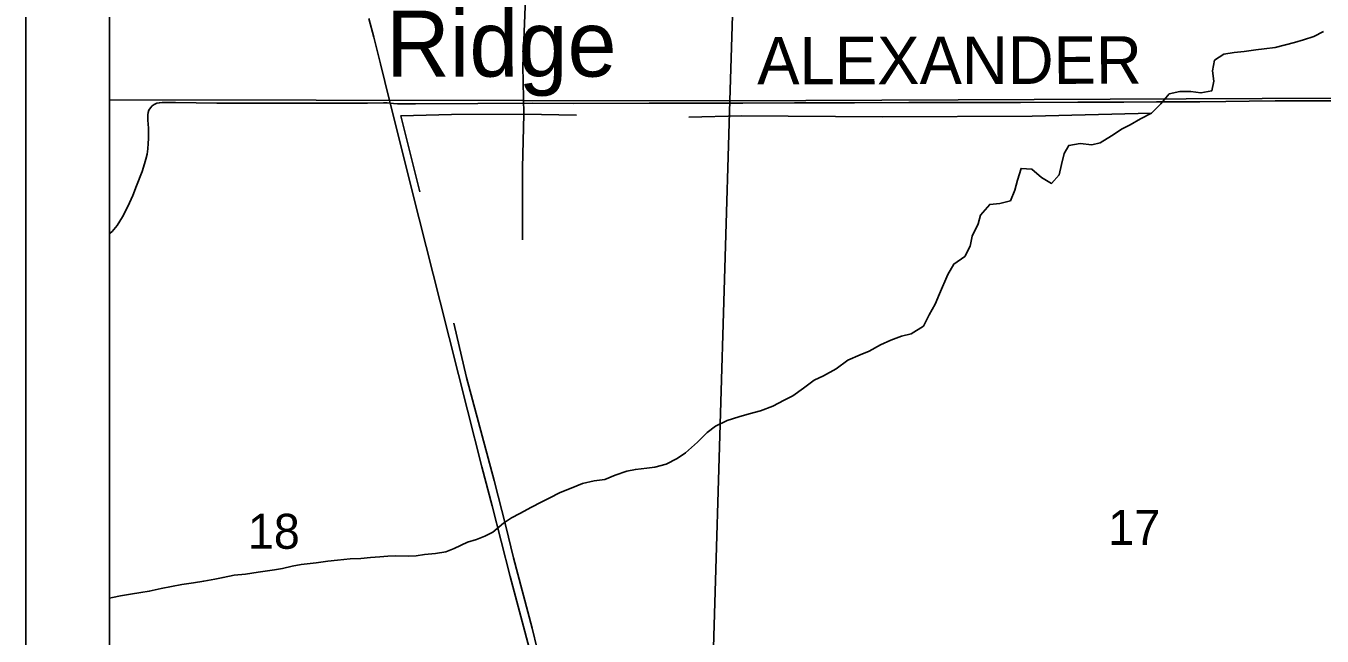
# Model space of a CAD drawing. Extents: x -8.3 to 42.1, y 0 to 22.
# Drawn here: x 2 to 3.551, y 15.682 to 16.412 of the extents above; entities that cross this region are included whole.
import ezdxf

# ---------------------------------------------------------------- set-up
doc = ezdxf.new("R2010")
doc.units = 0
for name, color, linetype in [('Default', 7, 'Continuous'), ('GM_X_Minor_River', 7, 'Continuous'), ('GM_X_Section', 7, 'Continuous'), ('GM_X_Section_Text', 7, 'Continuous'), ('GM_X_State_Route', 7, 'Continuous'), ('GM_X_Township_Road', 7, 'Continuous'), ('GM_X_Township_Road_Text', 7, 'Continuous'), ('GM_X_Unincorporated_Text', 7, 'Continuous'), ('SH_Cut_Line', 7, 'Continuous'), ('SH_Data', 7, 'Continuous')]:
    doc.layers.add(name, color=color, linetype=linetype)

msp = doc.modelspace()

# ---------------------------------------------------------------- linework, layer by layer
at = {"layer": 'Default'}
for points in [[(2.1, 17.3208), (2.1, 16.3231), (2.8424, 16.322), (2.8735, 17.321)], [(2.1, 16.3231), (2.1, 15.3156), (2.8124, 15.3208), (2.8424, 16.322)]]:
    msp.add_lwpolyline(points, close=True, dxfattribs=at)
at = {"layer": 'GM_X_Minor_River'}
for points in [[(2.5965, 16.562), (2.595, 16.4953), (2.5974, 16.4348), (2.5947, 16.3634), (2.5957, 16.306), (2.5942, 16.2418), (2.5941, 16.1558)], [(3.5528, 16.4047), (3.5413, 16.3989), (3.529, 16.395), (3.518, 16.3915), (3.4949, 16.3859)], [(3.4949, 16.3859), (3.4816, 16.384), (3.4717, 16.3828), (3.458, 16.3809), (3.4458, 16.3797), (3.4336, 16.3778), (3.4224, 16.3705), (3.4201, 16.358), (3.4217, 16.3454), (3.419, 16.3337), (3.4061, 16.3314), (3.394, 16.3329), (3.3807, 16.3329), (3.3681, 16.3302), (3.3582, 16.3183), (3.3469, 16.3072), (3.3338, 16.3004), (3.3215, 16.2931), (3.3118, 16.2885), (3.2991, 16.2801), (3.2856, 16.2717), (3.2756, 16.2694), (3.2616, 16.2709), (3.2479, 16.2686), (3.2423, 16.2589), (3.2393, 16.2457), (3.2366, 16.2332), (3.2272, 16.2232), (3.2153, 16.23), (3.2038, 16.2402), (3.1909, 16.241), (3.1867, 16.227), (3.1833, 16.215), (3.1781, 16.2022), (3.1654, 16.1991), (3.1533, 16.198), (3.1423, 16.185), (3.1393, 16.1748), (3.1324, 16.1602), (3.1298, 16.1481), (3.1234, 16.1357), (3.1102, 16.1266), (3.103, 16.1142), (3.0933, 16.0909), (3.088, 16.0786), (3.0808, 16.0658), (3.074, 16.0523), (3.0593, 16.0433), (3.0478, 16.0405), (3.0348, 16.0356), (3.0225, 16.0302), (3.009, 16.0226), (2.9982, 16.018), (2.9836, 16.0116), (2.9696, 16.0013), (2.9546, 15.993), (2.9431, 15.9877), (2.9306, 15.9781), (2.9178, 15.969), (2.9075, 15.964), (2.8936, 15.9568), (2.879, 15.9511), (2.8656, 15.9473), (2.853, 15.9439), (2.8392, 15.9393), (2.825, 15.9329), (2.8152, 15.9252), (2.8035, 15.9137), (2.7891, 15.9008), (2.7794, 15.8939), (2.766, 15.8874), (2.7526, 15.8836), (2.743, 15.8824), (2.7293, 15.8809), (2.719, 15.8789), (2.7052, 15.8739), (2.6929, 15.869), (2.68, 15.8674), (2.6662, 15.864), (2.6524, 15.8584), (2.6394, 15.8534), (2.6263, 15.8466), (2.6166, 15.8419), (2.6051, 15.8358), (2.5912, 15.8282), (2.5812, 15.8231), (2.5715, 15.8166), (2.5587, 15.8059), (2.549, 15.8012), (2.5391, 15.7973), (2.5283, 15.7938), (2.5126, 15.7863), (2.5026, 15.7824), (2.49, 15.7805), (2.477, 15.779), (2.4668, 15.7777), (2.4573, 15.7773), (2.4428, 15.7777), (2.433, 15.7772), (2.4235, 15.7763), (2.4124, 15.7755)], [(2.4712, 16.213), (2.4487, 16.3041), (2.5091, 16.3054), (2.5957, 16.306), (2.659, 16.3049)], [(3.3469, 16.3072), (3.2041, 16.3037), (3.0249, 16.3028), (2.856, 16.3038), (2.7933, 16.3022)], [(2.5119, 16.0559), (2.5271, 15.9908), (2.5604, 15.8678), (2.5744, 15.8131), (2.5836, 15.7752), (2.6059, 15.6909), (2.6239, 15.617)], [(2.4124, 15.7755), (2.4006, 15.7743), (2.3881, 15.7739), (2.3729, 15.7725), (2.3614, 15.7713), (2.3473, 15.7694), (2.3294, 15.7672), (2.3187, 15.7653), (2.3069, 15.7626), (2.2974, 15.7609), (2.2779, 15.7581), (2.2627, 15.7558), (2.249, 15.7543), (2.236, 15.7517), (2.2261, 15.7497), (2.2127, 15.7474), (2.2005, 15.7451), (2.1864, 15.7432), (2.1742, 15.7409), (2.162, 15.7386), (2.1475, 15.7352), (2.1375, 15.7336), (2.125, 15.7317), (2.1131, 15.7297), (2.1036, 15.7277), (2.1, 15.7271)]]:
    msp.add_lwpolyline(points, dxfattribs=at)
at = {"layer": 'GM_X_Section'}
for points in [[(3.8739, 17.3266), (3.8435, 16.3264), (2.8424, 16.322), (2.8735, 17.321)], [(3.8435, 16.3264), (3.8127, 15.327), (2.8124, 15.3208), (2.8424, 16.322)]]:
    msp.add_lwpolyline(points, close=True, dxfattribs=at)
at = {"layer": 'GM_X_State_Route'}
msp.add_lwpolyline([(2.6062, 15.6524), (2.597, 15.6869), (2.5795, 15.753), (2.5578, 15.8373), (2.5456, 15.8839), (2.5285, 15.9517), (2.4956, 16.0813), (2.4706, 16.1808), (2.4619, 16.2154), (2.4437, 16.2878), (2.436, 16.319), (2.4348, 16.324), (2.4244, 16.3663), (2.4164, 16.3979), (2.4105, 16.4205)], dxfattribs=at)
at = {"layer": 'GM_X_Township_Road'}
for points in [[(3.9382, 20.9), (2.1, 20.9), (2.1, 15.312)], [(2.1, 16.1627), (2.1009, 16.1634), (2.1032, 16.1656), (2.1053, 16.1679), (2.1072, 16.1703), (2.1091, 16.1728), (2.1125, 16.178), (2.1157, 16.1833), (2.1201, 16.1916), (2.1241, 16.1999), (2.1278, 16.2085), (2.1325, 16.2201), (2.139, 16.2375), (2.142, 16.2464), (2.1436, 16.252), (2.1451, 16.2581), (2.1459, 16.2646), (2.1464, 16.2708), (2.1468, 16.2769), (2.1466, 16.2892), (2.1459, 16.2988), (2.1457, 16.3019), (2.1459, 16.305), (2.1462, 16.3078), (2.1472, 16.3108), (2.1489, 16.3136), (2.1512, 16.3159), (2.1535, 16.3175), (2.1568, 16.319), (2.1597, 16.3197), (2.1632, 16.3198), (2.1663, 16.32), (2.1788, 16.3199), (2.2285, 16.3191), (2.2659, 16.3191), (2.2845, 16.3191), (2.3031, 16.319), (2.3218, 16.3191), (2.3746, 16.319), (2.4088, 16.3193), (2.4278, 16.3196), (2.4321, 16.3194), (2.436, 16.319)], [(2.436, 16.319), (2.4398, 16.3188), (2.4447, 16.3185), (2.4661, 16.3185), (2.5407, 16.3189), (2.606, 16.319), (2.6557, 16.3189), (2.7458, 16.3191), (2.8204, 16.319), (2.8577, 16.3192), (2.9199, 16.3194), (2.9914, 16.3197), (3.0566, 16.3198), (3.0939, 16.32), (3.1312, 16.32), (3.1903, 16.32), (3.2587, 16.3203), (3.2927, 16.3203), (3.3138, 16.3204), (3.3528, 16.3206), (3.4047, 16.3208), (3.4358, 16.321), (3.4637, 16.3216), (3.4948, 16.3218), (3.529, 16.322), (3.5756, 16.3219)]]:
    msp.add_lwpolyline(points, dxfattribs=at)
at = {"layer": 'SH_Cut_Line'}
msp.add_lwpolyline([(7.9572, 20.9), (2.1, 20.9), (2.1, 14.1)], dxfattribs=at)
at = {"layer": 'SH_Data'}
for p, q in [((2, 21), (2, 14)), ((2.1, 20.9), (2.1, 14.1))]:
    msp.add_line(p, q, dxfattribs=at)

# ---------------------------------------------------------------- texts
at = {"layer": 'GM_X_Section_Text'}
for s, p in [('18', (2.2655, 15.786)), ('17', (3.2951, 15.7907))]:
    msp.add_text(s, height=0.04186, rotation=0, dxfattribs=at).set_placement(p)
at = {"layer": 'GM_X_Township_Road_Text'}
msp.add_text('ALEXANDER', height=0.05682, rotation=0.1125, dxfattribs=at).set_placement((2.8751, 16.3415))
at = {"layer": 'GM_X_Unincorporated_Text'}
msp.add_text('Ridge', height=0.07898, rotation=0, dxfattribs=at).set_placement((2.4309, 16.3509))

doc.saveas('drawing.dxf')
